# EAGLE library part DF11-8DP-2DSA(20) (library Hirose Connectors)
CONN, VERT, PTH, 8P, 4x2, 2mm PITCH
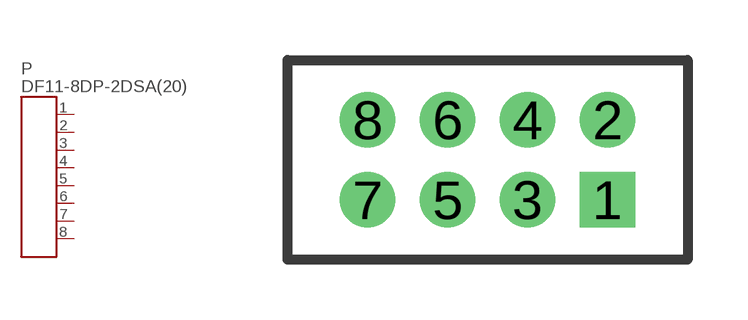
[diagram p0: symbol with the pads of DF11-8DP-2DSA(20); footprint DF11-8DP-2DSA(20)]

Designator prefix P

## DF11-8DP-2DSA(20)  [DF11-8DP-2DSA(20)]
1  P$1
2  P$2
3  P$3
4  P$4
5  P$5
6  P$6
7  P$7
8  P$8

## Footprint DF11-8DP-2DSA(20) (pad centres in mm)
drill 0.889 pad 1.27 square: 1 3,-1
drill 0.889 pad 1.27 round: 2 3,1; 3 1,-1; 4 1,1; 5 -1,-1; 6 -1,1; 7 -3,-1; 8 -3,1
